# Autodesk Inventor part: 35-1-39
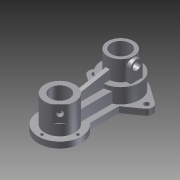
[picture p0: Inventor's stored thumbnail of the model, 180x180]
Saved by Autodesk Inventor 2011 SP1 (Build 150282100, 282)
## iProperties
Created: 2014-02
Part Number: 35-1-39
Document SubType Name: Modeling
Designer: Administrator
Density: 1 g/cm^3
Author: Administrator
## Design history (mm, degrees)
sketch "草图1"
  geometry: L1 (-29.462, 4.901)-(-12.115, 17.153); L2 (-29.462, -4.901)-(-12.115, -17.153); L3 (29.462, -4.901)-(12.115, -17.153); L4 (29.462, 4.901)-(12.115, 17.153); A1 r 6 centre (-26, 0) between (-29.462, 4.901) and (-29.462, -4.901); A2 r 6 centre (26, 0) between (29.462, -4.901) and (29.462, 4.901); A3 r 21 centre (0, 0) between (-12.115, -17.153) and (12.115, -17.153); A4 r 21 centre (0, 0) between (12.115, 17.153) and (-12.115, 17.153); 1 further point
  constraints: 8 end point, 8 point on circle, 4 centre point, 4 tangent, 1 coincident, 1 horizontal alignment
  dimensions: "d1" = 12 diameter of A1; "d2" = 26 distance of A3.centre A1.centre
extrude "拉伸1" new body sketch "草图1" distance "d3" = 6; taper "d4" = 0 deg
sketch "草图2"
  geometry: C1 r 21.5 at (0, -61); A1 r 21 centre (0, 0) between (12.115, 17.153) and (-12.115, 17.153) reference
  constraints: 1 centre point
  dimensions: "d5" = 43 diameter of C1; "d6" = 61 distance of A1.centre C1.centre
extrude "拉伸2" join sketch "草图2" distance "d7" = 6; taper "d8" = 0 deg
sketch "草图3"
  geometry: L1 (14, 16.317)-(14, 45.178); L2 (-14, 45.178)-(-14, 16.317); L3 (-29.462, 56.099)-(-12.115, 43.847) reference; L4 (12.115, 43.847)-(29.462, 56.099) reference; A1 r 21.5 centre (0, 0) between (-14, 16.317) and (14, 16.317) reference; A2 r 21 centre (0, 61) between (-12.115, 43.847) and (12.115, 43.847) reference; 2 further points
  constraints: 4 end point, 2 point on circle, 2 point on line, 1 parallel, 1 vertical alignment
extrude "拉伸3" join sketch "草图3" distance "d10" = 6; taper "d11" = 0 deg
sketch "草图4"
  geometry: C1 r 19 at (0, 0); A1 r 21 centre (0, 0) between (12.115, 17.153) and (-12.115, 17.153) reference
  constraints: 1 centre point, 1 coincident
  dimensions: "d12" = 38 diameter of C1
extrude "拉伸4" join sketch "草图4" distance "d13" = 15; taper "d14" = 0 deg
sketch "草图5"
  geometry: C1 r 19 at (0, 0) reference; C2 r 13 at (0, 0)
  constraints: 1 centre point, 1 coincident
  dimensions: "d15" = 26 diameter of C2
extrude "拉伸5" join sketch "草图5" distance "d16" = 20; taper "d17" = 0 deg
sketch "草图6"
  geometry: C1 r 15 at (0, -61); A1 r 21.5 centre (0, -61) between (-14, -44.683) and (14, -44.683) reference
  constraints: 1 centre point, 1 coincident
  dimensions: "d18" = 30 diameter of C1
extrude "拉伸6" join sketch "草图6" distance "d19" = 27; taper "d20" = 0 deg
sketch "草图7"
  geometry: L1 (8.5, -48.641)-(8.5, -16.993); L2 (-8.5, -16.993)-(-8.5, -48.641); A1 r 15 centre (0, -61) between (8.5, -48.641) and (-8.5, -48.641) reference; A2 r 19 centre (0, 0) between (-8.5, -16.993) and (8.5, -16.993) reference; 1 further point
  constraints: 4 end point, 4 point on circle, 1 parallel, 1 vertical alignment
extrude "拉伸7" join sketch "草图7" distance "d22" = 11; taper "d23" = 0 deg
sketch "草图8"
  geometry: L1 (-46, 17)-(-46, 33) reference; L2 (-13, 21)-(-13, 41) reference; L3 (-46, 24.5)-(-13, 30.5); 1 further point
  constraints: 2 end point, 2 point on line
  dimensions: "d24" = 8.5 distance of L3.start L1.end; "d25" = 10.5 distance of L3.end L2.end
feature "加强筋1" sketch "草图8" dims "d26" = 1, "d27" = 4, "d28" = 0
hole "Hole1" diameter "d31" = 19; stored, may be unused: countersink angle "d35" = 90 deg, drill point angle "d37" = 0 deg; dims "d29" = 10, "d30" = 10, "d32" = 6, "d33" = 30, "d34" = 18.5, "d36" = 8
hole "Hole2" diameter "d40" = 19; stored, may be unused: countersink angle "d44" = 90 deg, drill point angle "d46" = 118 deg; dims "d38" = 10, "d39" = 10, "d41" = 6, "d42" = 30, "d43" = 18.5, "d45" = 8
sketch "草图9"
  geometry: L1 (-6, -61)-(6, -61); L2 (6, -61)-(6, -1); L3 (6, -1)-(-6, -1); L4 (-6, -1)-(-6, -61); C1 r 9.5 at (0, -61) reference; 1 further point
  constraints: 8 end point, 2 parallel, 1 coincident, 1 horizontal, 1 midpoint, 1 perpendicular
  dimensions: "d47" = 12 distance of L2.end L3.end; "d48" = 60 distance of L3.end L1.start
extrude "拉伸8" cut sketch "草图9" distance "d49" = 13; taper "d50" = 0 deg
sketch "草图10"
  geometry: A1 r 21.5 centre (0, -61) between (-14, -44.683) and (14, -44.683) reference; 1 further point
  dimensions: "d51" = 18 distance of A1.centre point (-18, -61)
hole "Hole3" sketch "草图10" at (-18, -61) diameter "d52" = 3; stored, may be unused: countersink angle "d56" = 90 deg, drill point angle "d58" = 118 deg; dims "d53" = 6, "d54" = 30, "d55" = 18.5, "d57" = 8
node "工作轴1"
pattern_circular "环形阵列1" dims angle "d60" = 180 deg
sketch "草图11"
  geometry: C1 r 2.5 at (-26, 0); A1 r 6 centre (-26, 0) between (-29.462, 4.901) and (-29.462, -4.901) reference
  constraints: 1 centre point, 1 coincident
  dimensions: "d62" = 5 diameter of C1
extrude "拉伸9" cut sketch "草图11" stored distance "d63" = 13; taper "d64" = 0 deg
mirror "镜像1"
node "工作平面1"
sketch "草图12"
  geometry: L1 (-18.894, 21)-(19, 21) reference; L2 (-5.947, 33.896)-(-5.947, 21); L3 (6.053, 33.896)-(6.053, 21); A1 r 6 centre (0.053, 33.896) between (6.053, 33.896) and (-5.947, 33.896); 1 further point
  constraints: 4 end point, 2 point on circle, 2 point on line, 2 tangent, 1 centre point, 1 parallel, 1 perpendicular
  dimensions: "d66" = 12 diameter of A1
extrude "拉伸10" join sketch "草图12" stored distance "d67" = 13; taper "d68" = 0 deg
hole "Hole4" diameter "d71" = 8; stored, may be unused: countersink angle "d75" = 90 deg, drill point angle "d77" = 0 deg; dims "d69" = 10, "d70" = 10, "d72" = 6, "d73" = 30, "d74" = 18.5, "d76" = 10
sketch "草图14"
  geometry: L1 (6.092, -13.707)-(13.707, -6.092); C1 r 9.5 at (0, 0) reference; A1 r 15 centre (0, 0) between (6.092, -13.707) and (13.707, -6.092) reference; 1 further point
  constraints: 2 end point, 2 point on circle
  dimensions: "d83" = 14 distance from line of C1.centre L1
extrude "拉伸11" cut sketch "草图14" distance "d84" = 16; taper "d85" = 0 deg
sketch "草图15"
  geometry: L1 (10.77, 0)-(0, 0) reference; C1 r 3 at (5.385, 8); 1 further point
  constraints: 1 centre point
  dimensions: "d86" = 6 diameter of C1; "d87" = 8 distance from line of L1 C1.centre
extrude "拉伸12" cut sketch "草图15" distance "d88" = 16; taper "d89" = 0 deg
node "实体1"
other parameters: "d0" = 42, "d65" = 16, "d79" = 45 deg, "d80" = 14
